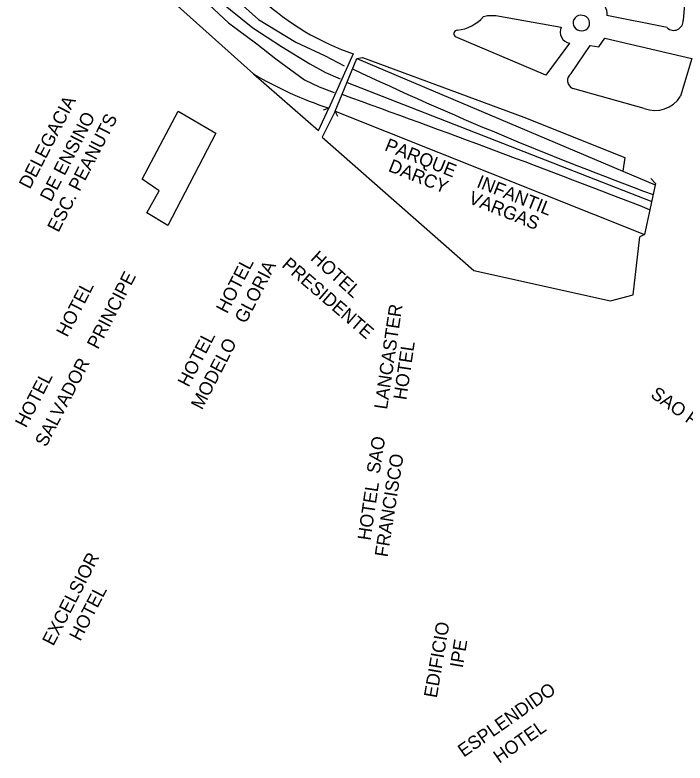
# Model space of a CAD drawing. Extents: x 325899 to 363134, y 7578590 to 7592502.
# Drawn here: x 337673.3 to 337876.2, y 7589770.7 to 7589997.3 of the extents above; entities that cross this region are included whole.
import ezdxf

# ---------------------------------------------------------------- set-up
doc = ezdxf.new("R2010")
doc.units = 0
for name, color, linetype in [('EDIFEXISTENT', 7, 'Continuous'), ('EDIFIDENTIF', 7, 'Continuous'), ('EDIFOBRAEXIS', 7, 'Continuous')]:
    doc.layers.add(name, color=color, linetype=linetype)

msp = doc.modelspace()

# ---------------------------------------------------------------- linework, layer by layer
at = {"layer": 'EDIFEXISTENT'}
for p, q in [((337775.69, 7589985.54), (337768.31, 7589969.08)), ((337775.69, 7589985.54), (337775.69, 7589985.54)), ((337770.29, 7589968.15), (337776.78, 7589984.06)), ((337776.78, 7589984.06), (337778.56, 7589984.4)), ((337711.82, 7589947.6), (337722.75, 7589968.16)), ((337722.75, 7589968.16), (337734.08, 7589961.46)), ((337768.31, 7589969.08), (337766.66, 7589968.49)), ((337771.06, 7589966.55), (337770.29, 7589968.15)), ((337734.08, 7589961.46), (337719.6, 7589933.48)), ((337716.99, 7589944.06), (337711.82, 7589947.6)), ((337865.91, 7589947.8), (337867.34, 7589946.2)), ((337867.34, 7589946.2), (337863.95, 7589930.75)), ((337713.23, 7589937.36), (337716.99, 7589944.06)), ((337719.6, 7589933.48), (337713.23, 7589937.36)), ((337863.95, 7589930.75), (337862.58, 7589930.11))]:
    msp.add_line(p, q, dxfattribs=at)
at = {"layer": 'EDIFOBRAEXIS'}
for points in [[(337720.58, 7590001.91), (337745.49, 7589979.44), (337765.23, 7589962.25), (337768.31, 7589969.08)], [(337730.6, 7590001.91), (337737.94, 7589994.9), (337746.5, 7589988.52), (337752.34, 7589984.03), (337760.93, 7589977.65), (337765.41, 7589975.56), (337769.95, 7589973.76)], [(337734.91, 7590001.91), (337745.29, 7589993.42), (337754.06, 7589987.7), (337762.59, 7589982.44), (337767.31, 7589979.81), (337771.76, 7589977.97)], [(337740.47, 7590001.91), (337747.06, 7589995.92), (337758.38, 7589989.09), (337767.19, 7589984.92), (337773, 7589981.84)], [(337876.19, 7590001.91), (337875.65, 7589995.64)], [(337815.22, 7589996.77), (337816.36, 7589997.16), (337818.98, 7589997.14), (337838.7, 7589993.62)], [(337870.8, 7589993.44), (337852.6, 7589997.12)], [(337841.26, 7589988.72), (337834.12, 7589979.06), (337806.74, 7589990.62)], [(337841.75, 7589979.51), (337847.47, 7589988), (337850.12, 7589987.65), (337851.94, 7589990.25), (337878.26, 7589984.05)], [(337776.78, 7589984.06), (337857.39, 7589949.94), (337867.19, 7589945.88)], [(337778.56, 7589984.4), (337827.45, 7589966.38), (337858.02, 7589954.09), (337857.39, 7589949.94)], [(337878.26, 7589984.05), (337874.91, 7589972.65)], [(337773.95, 7589976.85), (337866.18, 7589940.76)], [(337863.91, 7589968.98), (337842.3, 7589975.01)], [(337770.29, 7589968.15), (337766.33, 7589960.26), (337812.29, 7589919.94), (337853.63, 7589910.67), (337860.51, 7589912.55)], [(337770.29, 7589968.15), (337863.95, 7589930.75)], [(337860.51, 7589912.55), (337862.58, 7589930.11)]]:
    msp.add_lwpolyline(points, dxfattribs=at)
for centre, radius, start, end in [((337801.56, 7590060.48), 79.28, 227.6256, 250.9516), ((337848.08, 7589997.6), 4.55, 353.967, 71.3717), ((337805.96, 7590004.98), 12.37, 276.0808, 318.4335), ((337844.61, 7589994.89), 2.3, 75.6944, 261.0551), ((337845.03, 7589994.8), 2.32, 250.4014, 86.3481), ((337872.81, 7589995.46), 2.85, 225.2804, 3.5637), ((337807.28, 7589991.58), 1.1, 90.2087, 241.086), ((337842, 7589992.22), 3.58, 156.9855, 258.1586), ((338266.81, 7591028.73), 1157.25, 244.87606, 249.76659), ((337805.11, 7590080.52), 117.36, 239.4646, 251.7224), ((337843.24, 7589977.41), 2.58, 125.4244, 248.4716), ((336402.95, 7586173.27), 4039.14, 68.77107, 70.18186), ((337867.17, 7589977.53), 9.15, 249.1349, 327.7808)]:
    msp.add_arc(centre, radius, start, end, dxfattribs=at)

# ---------------------------------------------------------------- texts
at = {"layer": 'EDIFIDENTIF'}
for s, rotation, p in [('DELEGACIA', 62.6351, (337677.79, 7589944.29)), ('DE ENSINO', 62.6351, (337684.18, 7589940.47)), ('ESC. PEANUTS', 62.6351, (337686.41, 7589931.21)), ('PARQUE     INFANTIL', 338.2355, (337784.98, 7589956.38)), ('DARCY     VARGAS', 338.2355, (337786.1, 7589950.07)), ('PRESIDENTE', 319.2921, (337753.85, 7589921.2)), ('HOTEL', 317.8293, (337762.57, 7589923.3)), ('HOTEL', 62.6351, (337737.52, 7589906.61)), ('GLORIA', 62.6351, (337743.15, 7589903.58)), ('PRINCIPE', 62.6351, (337698.43, 7589895.79)), ('HOTEL', 62.6351, (337689.1, 7589899.47)), ('LANCASTER', 81.6117, (337785.99, 7589877.65)), ('HOTEL', 62.6351, (337725.86, 7589884.34)), ('MODELO', 62.6351, (337729.92, 7589877.48)), ('HOTEL', 81.6117, (337791.8, 7589880.52)), ('SALVADOR', 62.6351, (337682.68, 7589866.19)), ('HOTEL', 62.6351, (337676.63, 7589872.02)), ('SAO PAULO', 324.8172, (337865.52, 7589881.73)), ('SAO', 80.9312, (337783.7, 7589858.18)), ('FRANCISCO', 81.0615, (337786.14, 7589832.94)), ('HOTEL', 81.5655, (337780.96, 7589837.97)), ('EXCELSIOR', 62.6351, (337684.88, 7589805.96)), ('HOTEL', 62.6351, (337693.05, 7589807.41)), ('EDIFICIO', 80.3451, (337801.04, 7589790.28)), ('IPE', 80.4374, (337808.9, 7589799.35)), ('ESPLENDIDO', 34.9809, (337809.2, 7589772.34)), ('HOTEL', 34.9809, (337819.97, 7589770.48))]:
    msp.add_text(s, height=4, rotation=rotation, dxfattribs=at).set_placement(p)

doc.saveas('drawing.dxf')
